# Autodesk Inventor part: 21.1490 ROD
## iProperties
Created: 2012-03
Part Number: 21.1490 ROD
Document SubType Name: Modeling
Designer: Administrator
Density: 7.85 g/cm^3
Material: Steel
Mass: 474.685 g
Surface Area: 305.541 cm^2
Volume: 60.4694 cm^3
Author: Administrator
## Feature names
1. Base1
